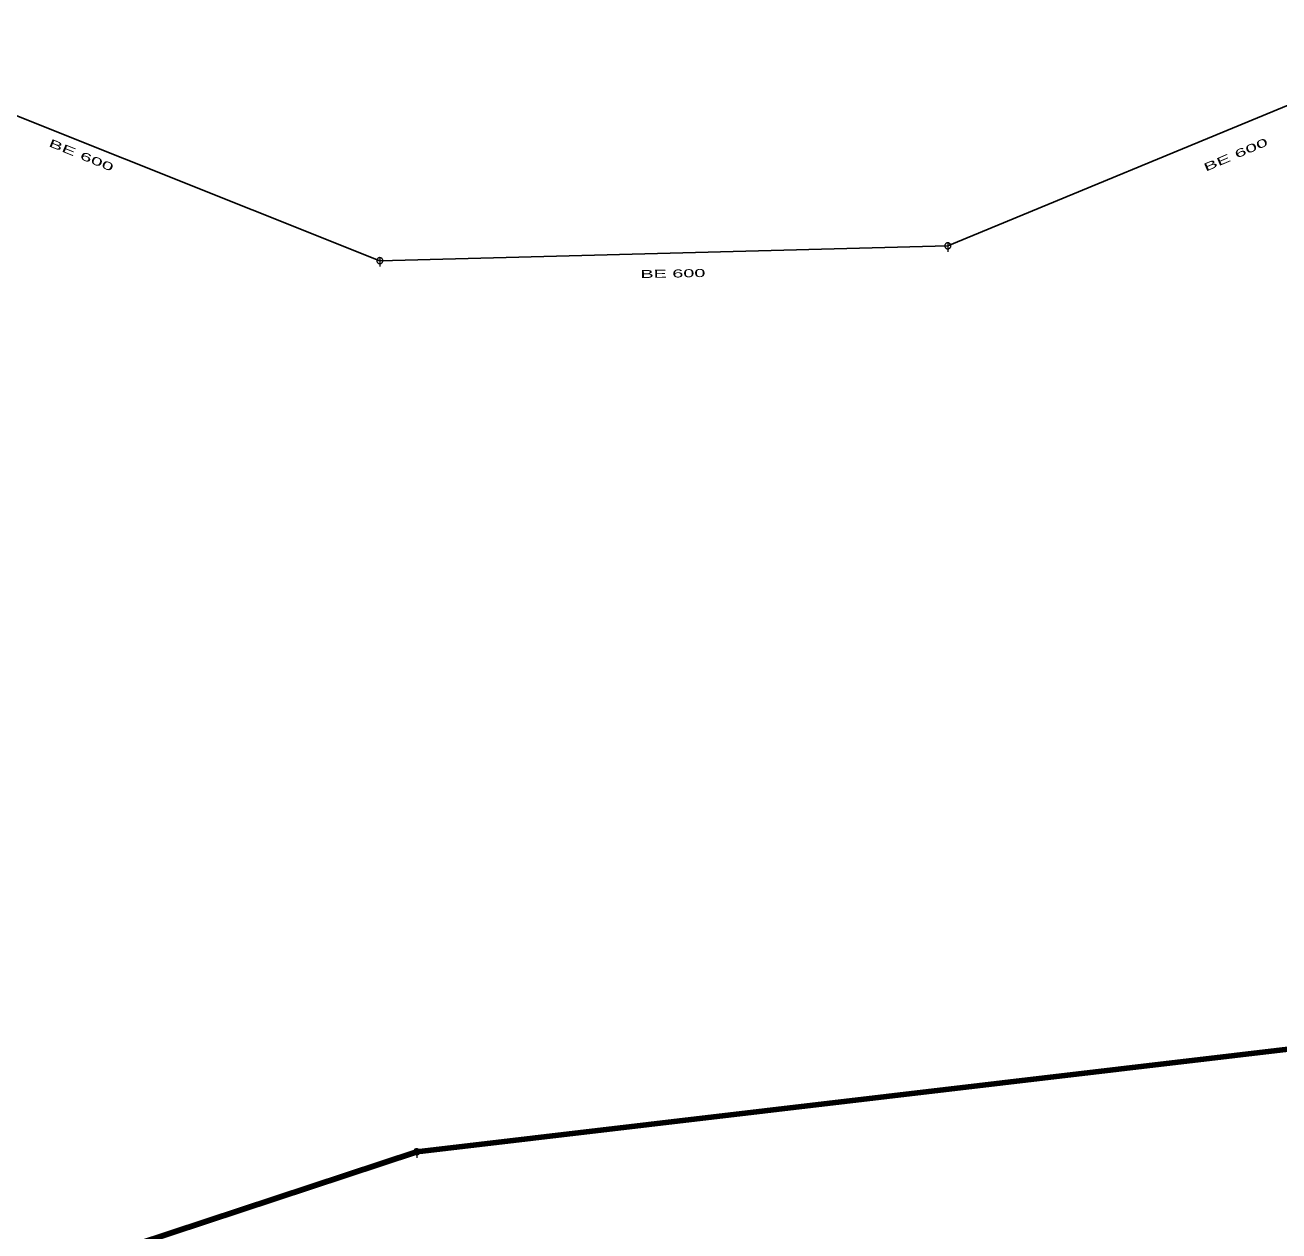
# Model space of a CAD drawing. Extents: x -687468 to -685917, y -974192 to -973456.
# Drawn here: x -686641.8 to -686537.4, y -974010.3 to -973909.9 of the extents above; entities that cross this region are included whole.
import ezdxf
from ezdxf.enums import TextEntityAlignment as Align

# ---------------------------------------------------------------- set-up
doc = ezdxf.new("R2010")
doc.units = 0
doc.header["$LTSCALE"] = 0.27
for name, color, linetype, lineweight in [('1', 7, 'Continuous', 13), ('14', 7, 'Continuous', 25), ('22', 7, 'Continuous', 13), ('27', 7, 'Continuous', 158)]:
    doc.layers.add(name, color=color, linetype=linetype, lineweight=lineweight)

msp = doc.modelspace()

# ---------------------------------------------------------------- linework, layer by layer
at = {"layer": '14'}
for p, q in [((-686612.298, -973929.522), (-686660.302, -973910.374)), ((-686520.577, -973909.902), (-686564.996, -973928.285)), ((-686564.996, -973928.285), (-686612.298, -973929.522)), ((-686200.654, -973955.608), (-686609.228, -974003.734)), ((-686609.228, -974003.734), (-687014.163, -974137.428))]:
    msp.add_line(p, q, dxfattribs=at)
at = {"layer": '22'}
for p, q in [((-686564.995, -973928.033), (-686564.996, -973928.777)), ((-686612.297, -973929.27), (-686612.298, -973930.014)), ((-686609.227, -974003.482), (-686609.228, -974004.226))]:
    msp.add_line(p, q, dxfattribs=at)
for points in [[(-686564.744, -973928.285), (-686564.745, -973928.259), (-686564.749, -973928.233), (-686564.755, -973928.207), (-686564.765, -973928.183), (-686564.777, -973928.159), (-686564.791, -973928.137), (-686564.808, -973928.116), (-686564.826, -973928.098), (-686564.847, -973928.081), (-686564.869, -973928.067), (-686564.893, -973928.055), (-686564.917, -973928.045), (-686564.943, -973928.039), (-686564.969, -973928.035), (-686564.995, -973928.033), (-686565.021, -973928.034), (-686565.047, -973928.038), (-686565.073, -973928.044), (-686565.098, -973928.054), (-686565.121, -973928.066), (-686565.143, -973928.08), (-686565.164, -973928.097), (-686565.182, -973928.115), (-686565.199, -973928.136), (-686565.213, -973928.158), (-686565.225, -973928.182), (-686565.235, -973928.206), (-686565.242, -973928.232), (-686565.246, -973928.258), (-686565.248, -973928.284), (-686565.247, -973928.31), (-686565.243, -973928.336), (-686565.236, -973928.362), (-686565.226, -973928.387), (-686565.214, -973928.41), (-686565.2, -973928.432), (-686565.183, -973928.453), (-686565.165, -973928.471), (-686565.144, -973928.488), (-686565.122, -973928.502), (-686565.099, -973928.514), (-686565.074, -973928.524), (-686565.048, -973928.531), (-686565.022, -973928.535), (-686564.996, -973928.537), (-686564.97, -973928.536), (-686564.944, -973928.532), (-686564.918, -973928.525), (-686564.894, -973928.515), (-686564.87, -973928.503), (-686564.848, -973928.489), (-686564.827, -973928.472), (-686564.809, -973928.454), (-686564.792, -973928.433), (-686564.778, -973928.411), (-686564.766, -973928.388), (-686564.756, -973928.363), (-686564.75, -973928.337), (-686564.746, -973928.311)], [(-686612.046, -973929.522), (-686612.047, -973929.496), (-686612.051, -973929.47), (-686612.057, -973929.444), (-686612.067, -973929.42), (-686612.079, -973929.396), (-686612.093, -973929.374), (-686612.11, -973929.353), (-686612.128, -973929.335), (-686612.149, -973929.318), (-686612.171, -973929.304), (-686612.195, -973929.292), (-686612.219, -973929.282), (-686612.245, -973929.276), (-686612.271, -973929.272), (-686612.297, -973929.27), (-686612.323, -973929.271), (-686612.349, -973929.275), (-686612.375, -973929.281), (-686612.4, -973929.291), (-686612.423, -973929.303), (-686612.445, -973929.317), (-686612.466, -973929.334), (-686612.484, -973929.352), (-686612.501, -973929.373), (-686612.515, -973929.395), (-686612.527, -973929.419), (-686612.537, -973929.443), (-686612.544, -973929.469), (-686612.548, -973929.495), (-686612.549, -973929.521), (-686612.549, -973929.547), (-686612.545, -973929.573), (-686612.538, -973929.599), (-686612.528, -973929.624), (-686612.516, -973929.647), (-686612.502, -973929.669), (-686612.485, -973929.69), (-686612.467, -973929.708), (-686612.446, -973929.725), (-686612.424, -973929.739), (-686612.401, -973929.751), (-686612.376, -973929.761), (-686612.35, -973929.768), (-686612.324, -973929.772), (-686612.298, -973929.774), (-686612.272, -973929.773), (-686612.246, -973929.769), (-686612.22, -973929.762), (-686612.196, -973929.752), (-686612.172, -973929.74), (-686612.15, -973929.726), (-686612.129, -973929.709), (-686612.111, -973929.691), (-686612.094, -973929.67), (-686612.08, -973929.648), (-686612.068, -973929.625), (-686612.058, -973929.6), (-686612.052, -973929.574), (-686612.048, -973929.548)], [(-686608.976, -974003.734), (-686608.977, -974003.708), (-686608.981, -974003.682), (-686608.987, -974003.656), (-686608.997, -974003.632), (-686609.009, -974003.608), (-686609.023, -974003.586), (-686609.04, -974003.565), (-686609.058, -974003.547), (-686609.079, -974003.53), (-686609.101, -974003.516), (-686609.125, -974003.504), (-686609.149, -974003.494), (-686609.175, -974003.488), (-686609.201, -974003.484), (-686609.227, -974003.482), (-686609.253, -974003.483), (-686609.279, -974003.487), (-686609.305, -974003.493), (-686609.33, -974003.503), (-686609.353, -974003.515), (-686609.375, -974003.529), (-686609.396, -974003.546), (-686609.414, -974003.564), (-686609.431, -974003.585), (-686609.445, -974003.607), (-686609.457, -974003.631), (-686609.467, -974003.655), (-686609.474, -974003.681), (-686609.478, -974003.707), (-686609.48, -974003.733), (-686609.479, -974003.759), (-686609.475, -974003.785), (-686609.468, -974003.811), (-686609.458, -974003.836), (-686609.446, -974003.859), (-686609.432, -974003.881), (-686609.415, -974003.902), (-686609.397, -974003.92), (-686609.376, -974003.937), (-686609.354, -974003.951), (-686609.331, -974003.963), (-686609.306, -974003.973), (-686609.28, -974003.98), (-686609.254, -974003.984), (-686609.228, -974003.986), (-686609.202, -974003.985), (-686609.176, -974003.981), (-686609.15, -974003.974), (-686609.126, -974003.964), (-686609.102, -974003.952), (-686609.08, -974003.938), (-686609.059, -974003.921), (-686609.041, -974003.903), (-686609.024, -974003.882), (-686609.01, -974003.86), (-686608.998, -974003.837), (-686608.988, -974003.812), (-686608.982, -974003.786), (-686608.978, -974003.76)]]:
    msp.add_lwpolyline(points, close=True, dxfattribs=at)
at = {"layer": '27'}
msp.add_lwpolyline([(-686200.654, -973955.608), (-686609.228, -974003.734), (-687014.163, -974137.428)], dxfattribs=at)
msp.add_lwpolyline([(-686200.654, -973955.608), (-686609.228, -974003.734), (-687014.163, -974137.428)], dxfattribs=at)

# ---------------------------------------------------------------- texts
at = {"layer": '1'}
for rotation, width, p in [(338, 1.95, (-686637.285, -973921.042)), (23, 1.95, (-686540.892, -973921)), (1, 1.85, (-686587.887, -973930.926))]:
    msp.add_text('BE 600', height=0.6667, rotation=rotation, dxfattribs=dict(at, width=width)).set_placement(p, align=Align.CENTER)

doc.saveas('drawing.dxf')
